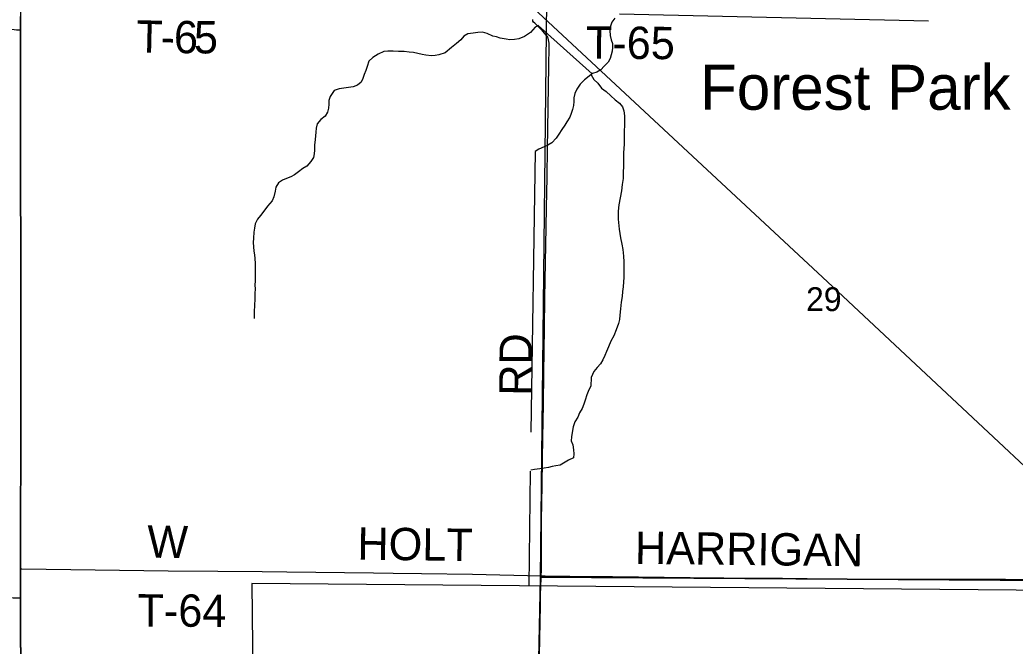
# Model space of a CAD drawing. Extents: x 0 to 34, y 0 to 22.
# Drawn here: x 4.702 to 6.452, y 15.265 to 16.366 of the extents above; entities that cross this region are included whole.
import ezdxf

# ---------------------------------------------------------------- set-up
doc = ezdxf.new("R2010")
doc.units = 0
for name, color, linetype in [('GM_X_County_Road', 7, 'Continuous'), ('GM_X_Interstate_Route', 7, 'Continuous'), ('GM_X_Major_River', 7, 'Continuous'), ('GM_X_Minor_River', 7, 'Continuous'), ('GM_X_Rail_Line', 7, 'Continuous'), ('GM_X_Section', 7, 'Continuous'), ('GM_X_Section_Text', 7, 'Continuous'), ('GM_X_Township_Road', 7, 'Continuous'), ('GM_X_Township_Road_Text', 7, 'Continuous'), ('GM_X_Unincorporated_Text', 7, 'Continuous')]:
    doc.layers.add(name, color=color, linetype=linetype)

msp = doc.modelspace()

# ---------------------------------------------------------------- linework, layer by layer
at = {"layer": 'GM_X_County_Road'}
for points in [[(4.704, 16.3481), (4.704, 16.3712), (4.704, 16.4084)], [(4.7038, 15.4001), (4.7036, 15.4418), (4.704, 15.5008), (4.7042, 15.591), (4.7041, 15.6905), (4.7041, 15.8148), (4.7042, 15.8645), (4.7041, 15.9205), (4.7043, 15.9764), (4.7038, 16.0635), (4.7038, 16.1412), (4.7039, 16.194), (4.7041, 16.222), (4.7039, 16.2873), (4.704, 16.3481)], [(4.7038, 15.3493), (4.7039, 15.392), (4.7038, 15.4001)], [(4.7052, 14.3464), (4.7054, 14.3911), (4.7054, 14.4409), (4.7054, 14.4719), (4.7052, 14.4954), (4.7049, 14.5933), (4.7052, 14.6897), (4.7058, 14.7393), (4.7056, 14.8947), (4.7054, 14.9662), (4.705, 15.0377), (4.7049, 15.0843), (4.7046, 15.162), (4.7042, 15.2366), (4.7035, 15.2867), (4.7038, 15.3361), (4.7038, 15.3493)]]:
    msp.add_lwpolyline(points, dxfattribs=at)
at = {"layer": 'GM_X_Interstate_Route'}
for points in [[(4.704, 15.2372), (4.7033, 15.2872), (4.7036, 15.3367), (4.7036, 15.3498), (4.7037, 15.3926), (4.7036, 15.4006), (4.7034, 15.4423), (4.7037, 15.5014), (4.7039, 15.5915), (4.7039, 15.691), (4.7039, 15.8154), (4.704, 15.8651), (4.7039, 15.921), (4.704, 15.977), (4.7036, 16.064), (4.7036, 16.1417), (4.7036, 16.1946), (4.7038, 16.2226), (4.7037, 16.2878), (4.7038, 16.3486), (4.7038, 16.3718)], [(4.7038, 16.3718), (4.7038, 16.3486), (4.7037, 16.2878), (4.7038, 16.2226), (4.7036, 16.1946), (4.7036, 16.1417), (4.7036, 16.064), (4.704, 15.977), (4.7039, 15.921), (4.704, 15.8651), (4.7039, 15.8154), (4.7039, 15.691), (4.7039, 15.5915), (4.7037, 15.5014), (4.7034, 15.4423), (4.7036, 15.4006), (4.7037, 15.3926), (4.7036, 15.3498), (4.7036, 15.3367), (4.7033, 15.2872), (4.704, 15.2372)]]:
    msp.add_lwpolyline(points, dxfattribs=at)
at = {"layer": 'GM_X_Major_River'}
msp.add_lwpolyline([(5.7478, 16.3688), (5.7425, 16.3616), (5.7403, 16.3544), (5.7395, 16.3468), (5.7399, 16.3381), (5.7418, 16.3305), (5.7437, 16.324), (5.744, 16.3172), (5.7433, 16.3107), (5.7414, 16.3043), (5.7399, 16.2978), (5.7361, 16.2914), (5.7296, 16.2842), (5.7235, 16.2777), (5.7163, 16.2736), (5.7091, 16.2713), (5.6947, 16.2599), (5.6872, 16.2523), (5.6815, 16.2436), (5.6777, 16.2364), (5.6761, 16.2284), (5.6761, 16.2219), (5.6754, 16.2151), (5.6739, 16.2083), (5.6716, 16.2011), (5.6689, 16.1946), (5.6636, 16.1866), (5.6602, 16.1802), (5.6549, 16.173), (5.6496, 16.1646), (5.6447, 16.1574), (5.6371, 16.1494), (5.6306, 16.1453), (5.6238, 16.1422), (5.6143, 16.1384), (5.6079, 16.1339)], dxfattribs=at)
at = {"layer": 'GM_X_Minor_River'}
for points in [[(6.2994, 16.3632), (5.7562, 16.3757)], [(5.6133, 16.3556), (5.6083, 16.3526), (5.6, 16.3435), (5.5894, 16.3363), (5.5795, 16.3325), (5.5719, 16.331), (5.5636, 16.3306), (5.5572, 16.3314), (5.5465, 16.3337), (5.5401, 16.3356), (5.5337, 16.3371), (5.5238, 16.3417), (5.5155, 16.3439), (5.5071, 16.3432), (5.4988, 16.3421), (5.4897, 16.3413), (5.4829, 16.3368), (5.4772, 16.3303), (5.47, 16.3242), (5.4609, 16.317), (5.4499, 16.3079), (5.4389, 16.3041), (5.4324, 16.303), (5.426, 16.3026), (5.4157, 16.3034), (5.4093, 16.3045), (5.4017, 16.3064), (5.3945, 16.308), (5.3869, 16.3091), (5.3778, 16.3099), (5.368, 16.3102), (5.3585, 16.3106), (5.349, 16.3106), (5.3422, 16.3099), (5.332, 16.3053), (5.3229, 16.2996), (5.3157, 16.2932), (5.313, 16.2837), (5.3104, 16.2765), (5.3073, 16.2693), (5.3054, 16.2628), (5.3024, 16.256), (5.2959, 16.2507), (5.288, 16.248), (5.28, 16.2469), (5.2717, 16.2458), (5.2633, 16.2442), (5.255, 16.2416), (5.2478, 16.231), (5.2455, 16.2238), (5.2455, 16.2173), (5.2448, 16.2101), (5.2432, 16.2036), (5.2391, 16.1964), (5.2315, 16.1903), (5.2247, 16.1828), (5.2231, 16.1752), (5.2224, 16.1683), (5.2216, 16.1554), (5.2205, 16.1452), (5.2201, 16.1364), (5.2197, 16.13), (5.2182, 16.1235), (5.214, 16.1167), (5.2068, 16.1083), (5.2, 16.1045), (5.192, 16.0985), (5.1848, 16.0932), (5.1784, 16.0898), (5.1708, 16.0867), (5.164, 16.0837), (5.1571, 16.0788), (5.1522, 16.0715), (5.1511, 16.0643), (5.1488, 16.0545), (5.1458, 16.0476), (5.1378, 16.0378), (5.1314, 16.0294), (5.1253, 16.0218), (5.12, 16.015), (5.1158, 16.007), (5.1147, 15.9994), (5.1139, 15.9922), (5.1128, 15.9816), (5.1124, 15.9744), (5.1131, 15.9664), (5.1139, 15.9592), (5.1147, 15.9523), (5.1154, 15.9459), (5.1158, 15.9375), (5.1158, 15.9064), (5.1154, 15.8996), (5.1158, 15.892), (5.1154, 15.8851), (5.1154, 15.8756), (5.115, 15.8627), (5.1142, 15.8532), (5.1142, 15.8464), (5.114, 15.8408)], [(5.7082, 16.2705), (5.6133, 16.3556)], [(5.7065, 16.2692), (5.711, 16.261), (5.7182, 16.2542), (5.7247, 16.2454), (5.7326, 16.2394), (5.741, 16.2321), (5.7489, 16.2249), (5.7561, 16.2192), (5.7614, 16.2128), (5.7637, 16.2055), (5.7652, 16.1968), (5.7652, 16.1888), (5.7648, 16.1793), (5.7645, 16.171), (5.7644, 16.16), (5.7644, 16.1471), (5.7633, 16.1319), (5.7633, 16.1087), (5.7629, 16.0969), (5.7625, 16.0867), (5.761, 16.0761), (5.7595, 16.065), (5.7572, 16.0525), (5.7553, 16.0404), (5.7542, 16.029), (5.7542, 16.0149), (5.7557, 15.9975), (5.7579, 15.9826), (5.7606, 15.9713), (5.7621, 15.9618), (5.7632, 15.9504), (5.7636, 15.9401), (5.7636, 15.9128), (5.7632, 15.9052), (5.7625, 15.8961), (5.7617, 15.8881), (5.7609, 15.879), (5.7594, 15.8691), (5.7583, 15.8573), (5.7571, 15.8463), (5.756, 15.8387), (5.7545, 15.8319), (5.7503, 15.8209), (5.7461, 15.8103), (5.7412, 15.8004), (5.737, 15.7905), (5.7332, 15.7826), (5.7306, 15.7753), (5.7268, 15.7677), (5.723, 15.7609), (5.7169, 15.7545), (5.7112, 15.7473), (5.7067, 15.737), (5.7059, 15.7218), (5.7021, 15.7154), (5.6987, 15.7066), (5.6957, 15.6968), (5.6938, 15.6899), (5.6904, 15.682), (5.6862, 15.6744), (5.6828, 15.6668), (5.6778, 15.6588), (5.6748, 15.6501), (5.6729, 15.6402), (5.6718, 15.6326), (5.6714, 15.6254), (5.6744, 15.6186), (5.6756, 15.6098), (5.6759, 15.6026), (5.6755, 15.5954), (5.6668, 15.5912), (5.6581, 15.5863), (5.6517, 15.5829), (5.6445, 15.5814), (5.638, 15.5802), (5.6312, 15.5787), (5.6236, 15.5772), (5.6164, 15.5761), (5.6069, 15.5753), (5.6005, 15.5738)], [(5.6079, 16.1339), (5.6005, 15.6406)], [(5.5993, 15.5719), (5.597, 15.3703)], [(6.7224, 15.3608), (5.1099, 15.3744), (5.1125, 15.1557), (4.6992, 15.1313)]]:
    msp.add_lwpolyline(points, dxfattribs=at)
at = {"layer": 'GM_X_Rail_Line'}
msp.add_lwpolyline([(4.6999, 17.2234), (5.1959, 16.7623), (5.6141, 16.3779), (6.1219, 15.9048), (6.7692, 15.2987), (7.1796, 14.9035), (7.6056, 14.5217)], dxfattribs=at)
at = {"layer": 'GM_X_Section'}
for points in [[(5.6285, 16.3977), (6.6138, 16.3837), (6.6049, 15.379), (5.6172, 15.3858)], [(6.5967, 14.3417), (5.5962, 14.3464), (5.6172, 15.3858), (6.6049, 15.379)]]:
    msp.add_lwpolyline(points, close=True, dxfattribs=at)
at = {"layer": 'GM_X_Township_Road'}
for points in [[(4.1369, 16.3622), (4.1773, 16.3614), (4.2016, 16.361), (4.2743, 16.3595), (4.3415, 16.3576), (4.3868, 16.3566), (4.4714, 16.3543), (4.5472, 16.3522), (4.6343, 16.35), (4.6922, 16.3484), (4.6964, 16.3483), (4.704, 16.3481)], [(5.6188, 15.3881), (5.619, 15.3979), (5.619, 15.4358), (5.6194, 15.4854), (5.6202, 15.5474), (5.6208, 15.5927), (5.6213, 15.6307), (5.6226, 15.6902), (5.6235, 15.7438), (5.6245, 15.8236), (5.6253, 15.8767), (5.6276, 16.0011), (5.6281, 16.0358), (5.6289, 16.0884), (5.6297, 16.1412), (5.6305, 16.172), (5.631, 16.2125), (5.6323, 16.284), (5.6328, 16.3182), (5.6324, 16.3245), (5.6321, 16.3276), (5.6317, 16.3306), (5.6311, 16.3332), (5.6305, 16.3349), (5.6296, 16.3363), (5.6276, 16.339), (5.6252, 16.3418), (5.6208, 16.3466), (5.6163, 16.3509), (5.6074, 16.3596), (5.6054, 16.3617), (5.6042, 16.3633), (5.6038, 16.3644), (5.6037, 16.3661)], [(4.7038, 15.4001), (4.7057, 15.4001), (4.7485, 15.3997), (4.7921, 15.3991), (4.963, 15.3971), (5.0503, 15.3965), (5.128, 15.3956), (5.1716, 15.3949), (5.324, 15.3934), (5.3582, 15.3928), (5.408, 15.3922), (5.4982, 15.391), (5.6188, 15.3881)], [(5.5973, 14.3344), (5.5974, 14.3452), (5.5987, 14.416), (5.5997, 14.4623), (5.6003, 14.5029), (5.6015, 14.558), (5.602, 14.5835), (5.6025, 14.6198), (5.6033, 14.6473), (5.6055, 14.7541), (5.6068, 14.8166), (5.6081, 14.8725), (5.6112, 15.022), (5.612, 15.0687), (5.6149, 15.2113), (5.6156, 15.2486), (5.6172, 15.3358), (5.6175, 15.3538), (5.6182, 15.3697), (5.6188, 15.3829), (5.6188, 15.3881)], [(5.6188, 15.3881), (5.6257, 15.388), (5.6692, 15.3872), (5.7439, 15.387), (5.8807, 15.3852), (5.9989, 15.3842), (6.0425, 15.3837), (6.1296, 15.3829), (6.2851, 15.3824), (6.3442, 15.3823), (6.4344, 15.3821), (6.4904, 15.3817), (6.5371, 15.3817), (6.6117, 15.3813)], [(3.7061, 15.3581), (3.7077, 15.3581), (3.7448, 15.3577), (3.7834, 15.357), (3.8567, 15.3561), (3.9089, 15.3556), (3.9506, 15.355), (4.0705, 15.3536), (4.1072, 15.3532), (4.2017, 15.352), (4.2427, 15.3518), (4.2819, 15.3515), (4.3198, 15.3513), (4.3639, 15.3511), (4.4031, 15.3511), (4.436, 15.3512), (4.4745, 15.3511), (4.5435, 15.3506), (4.5839, 15.3504), (4.6398, 15.3499), (4.6907, 15.3493), (4.7029, 15.3493), (4.7038, 15.3493)]]:
    msp.add_lwpolyline(points, dxfattribs=at)

# ---------------------------------------------------------------- texts
at = {"layer": 'GM_X_Section_Text'}
msp.add_text('29', height=0.04186, rotation=0, dxfattribs=at).set_placement((6.0842, 15.8536))
at = {"layer": 'GM_X_Township_Road_Text'}
for s, height, rotation, p in [('T', 0.0568, 358.6928, (4.9063, 16.3083)), ('6', 0.0568, 359.5542, (4.973, 16.3071)), ('5', 0.0568, 359.5866, (5.0081, 16.3068)), ('T-65', 0.05682, 359.644, (5.6971, 16.2974)), ('-', 0.0568, 359.4289, (4.9496, 16.3073)), ('RD', 0.05682, 89.5063, (5.6016, 15.7045)), ('W', 0.0568, 359.2835, (4.9261, 15.42)), ('HOLT', 0.05682, 359.2266, (5.2954, 15.4167)), ('HARRIGAN', 0.05682, 359.3529, (5.7832, 15.4092)), ('T-64', 0.05682, 359.6431, (4.909, 15.2991))]:
    msp.add_text(s, height=height, rotation=rotation, dxfattribs=at).set_placement(p)
at = {"layer": 'GM_X_Unincorporated_Text'}
msp.add_text('Forest Park', height=0.078977, rotation=0, dxfattribs=at).set_placement((5.8979, 16.2076))

doc.saveas('drawing.dxf')
